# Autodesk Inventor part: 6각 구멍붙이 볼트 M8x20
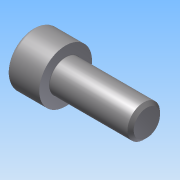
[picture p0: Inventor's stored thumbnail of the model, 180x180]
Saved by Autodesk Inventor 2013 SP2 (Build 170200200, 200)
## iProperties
Created: 2025-06
Part Number: 6각 구멍붙이 볼트 M8x20
Material: Generic
Document SubType Name: Modeling
Designer: a
Density: 1 g/cm^3
Author: a
변환 표준: STEP AP214IS
전처리기: Build: 200, Release: 2013 SP2 Update 6 - Date: Thu 07/17/2014
전송 단위: 밀리미터
불확실성: 0.01
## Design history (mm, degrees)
node "6각 구멍붙이 볼트 M8x201"
body "Solid1"
node "기준1"
